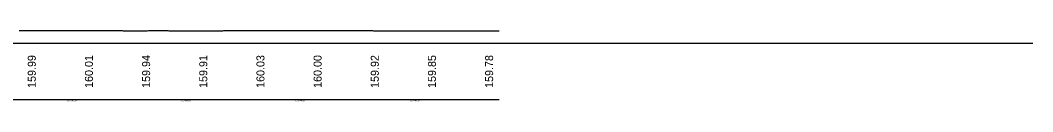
# Model space of a CAD drawing. Extents: x 2126510 to 2136144, y 865066 to 868066.
# Drawn here: x 2135258 to 2136144, y 867812 to 867874 of the extents above; entities that cross this region are included whole.
import ezdxf

# ---------------------------------------------------------------- set-up
doc = ezdxf.new("R2010")
doc.units = 0
doc.layers.add('RD_EX_Misc', color=7, linetype='Continuous')

msp = doc.modelspace()

# ---------------------------------------------------------------- linework, layer by layer
at = {"layer": 'RD_EX_Misc'}
msp.add_line((2131523, 867814.32), (2135677.25, 867814.32), dxfattribs=at)
for points in [[(2135257.47, 867874.35), (2135258.47, 867874.35), (2135259.47, 867874.35), (2135260.47, 867874.34), (2135261.47, 867874.34), (2135262.47, 867874.34), (2135263.47, 867874.33), (2135264.47, 867874.33), (2135265.47, 867874.33), (2135266.47, 867874.32), (2135267.47, 867874.32), (2135268.47, 867874.32), (2135269.47, 867874.32), (2135270.47, 867874.31), (2135271.47, 867874.31), (2135272.47, 867874.31), (2135273.47, 867874.3), (2135274.47, 867874.3), (2135275.47, 867874.3), (2135276.47, 867874.29), (2135277.47, 867874.29), (2135278.47, 867874.29), (2135279.47, 867874.29), (2135280.47, 867874.29), (2135281.47, 867874.29), (2135282.47, 867874.3), (2135283.47, 867874.3), (2135284.47, 867874.3), (2135285.47, 867874.3), (2135286.47, 867874.3)], [(2135286.47, 867874.3), (2135287.47, 867874.31), (2135288.47, 867874.31), (2135289.47, 867874.31), (2135290.47, 867874.31), (2135291.47, 867874.32), (2135292.47, 867874.32), (2135293.47, 867874.32), (2135294.47, 867874.32), (2135295.47, 867874.32), (2135296.47, 867874.33), (2135297.47, 867874.33), (2135298.47, 867874.33), (2135299.47, 867874.33), (2135300.47, 867874.33), (2135301.47, 867874.33), (2135302.47, 867874.33), (2135303.47, 867874.34), (2135304.47, 867874.34), (2135305.47, 867874.34), (2135306.47, 867874.34), (2135307.47, 867874.34), (2135308.47, 867874.34), (2135309.47, 867874.34), (2135310.47, 867874.34), (2135311.47, 867874.35), (2135312.47, 867874.35), (2135313.47, 867874.35), (2135314.47, 867874.35), (2135315.47, 867874.35), (2135316.47, 867874.35), (2135317.47, 867874.35), (2135318.47, 867874.34), (2135319.47, 867874.34), (2135320.47, 867874.33), (2135321.47, 867874.33), (2135322.47, 867874.33), (2135323.47, 867874.32), (2135324.47, 867874.32), (2135325.47, 867874.31), (2135326.47, 867874.31), (2135327.47, 867874.31), (2135328.47, 867874.3), (2135329.47, 867874.3), (2135330.47, 867874.29), (2135331.47, 867874.29), (2135332.47, 867874.28), (2135333.47, 867874.28), (2135334.47, 867874.28), (2135335.47, 867874.27), (2135336.47, 867874.27), (2135337.47, 867874.26), (2135338.47, 867874.26), (2135339.47, 867874.26), (2135340.47, 867874.26), (2135341.47, 867874.26), (2135342.47, 867874.26), (2135343.47, 867874.26), (2135344.47, 867874.25), (2135345.47, 867874.25), (2135346.47, 867874.25), (2135347.47, 867874.25), (2135348.47, 867874.24), (2135349.47, 867874.24), (2135350.47, 867874.24), (2135351.47, 867874.24), (2135352.47, 867874.24), (2135353.47, 867874.23), (2135354.47, 867874.23), (2135355.47, 867874.23), (2135356.47, 867874.23), (2135357.47, 867874.22), (2135358.47, 867874.22), (2135359.47, 867874.23), (2135360.47, 867874.23), (2135361.47, 867874.23), (2135362.47, 867874.23), (2135363.47, 867874.23), (2135364.47, 867874.24), (2135365.47, 867874.24), (2135366.47, 867874.24), (2135367.47, 867874.24), (2135368.47, 867874.24), (2135369.47, 867874.24), (2135370.47, 867874.25), (2135371.47, 867874.25), (2135372.47, 867874.25), (2135373.47, 867874.25), (2135374.47, 867874.25), (2135375.47, 867874.26), (2135376.47, 867874.26), (2135377.47, 867874.26), (2135378.47, 867874.26), (2135379.47, 867874.25), (2135380.47, 867874.25), (2135381.47, 867874.25), (2135382.47, 867874.25), (2135383.47, 867874.25), (2135384.47, 867874.25), (2135385.47, 867874.25), (2135386.47, 867874.25)], [(2135386.47, 867874.25), (2135387.47, 867874.25), (2135388.47, 867874.24), (2135389.47, 867874.24), (2135390.47, 867874.24), (2135391.47, 867874.24), (2135392.47, 867874.24), (2135393.47, 867874.24), (2135394.47, 867874.24), (2135395.47, 867874.24), (2135396.47, 867874.24), (2135397.47, 867874.23), (2135398.47, 867874.23), (2135399.47, 867874.23), (2135400.47, 867874.23), (2135401.47, 867874.23), (2135402.47, 867874.23), (2135403.47, 867874.23), (2135404.47, 867874.23), (2135405.47, 867874.23), (2135406.47, 867874.23), (2135407.47, 867874.23), (2135408.47, 867874.23), (2135409.47, 867874.22), (2135410.47, 867874.22), (2135411.47, 867874.22), (2135412.47, 867874.22), (2135413.47, 867874.22), (2135414.47, 867874.22), (2135415.47, 867874.22), (2135416.47, 867874.22), (2135417.47, 867874.22), (2135418.47, 867874.22), (2135419.47, 867874.22), (2135420.47, 867874.22), (2135421.47, 867874.22), (2135422.47, 867874.23), (2135423.47, 867874.23), (2135424.47, 867874.23), (2135425.47, 867874.23), (2135426.47, 867874.23), (2135427.47, 867874.23), (2135428.47, 867874.23), (2135429.47, 867874.24), (2135430.47, 867874.24), (2135431.47, 867874.24), (2135432.47, 867874.24), (2135433.47, 867874.24), (2135434.47, 867874.24), (2135435.47, 867874.24), (2135436.47, 867874.25), (2135437.47, 867874.25), (2135438.47, 867874.25), (2135439.47, 867874.25), (2135440.47, 867874.26), (2135441.47, 867874.26), (2135442.47, 867874.27), (2135443.47, 867874.27), (2135444.47, 867874.28), (2135445.47, 867874.28), (2135446.47, 867874.29), (2135447.47, 867874.29), (2135448.47, 867874.3), (2135449.47, 867874.3), (2135450.47, 867874.31), (2135451.47, 867874.31), (2135452.47, 867874.32), (2135453.47, 867874.32), (2135454.47, 867874.33), (2135455.47, 867874.33), (2135456.47, 867874.34), (2135457.47, 867874.34), (2135458.47, 867874.34), (2135459.47, 867874.34), (2135460.47, 867874.34), (2135461.47, 867874.34), (2135462.47, 867874.34), (2135463.47, 867874.34), (2135464.47, 867874.34), (2135465.47, 867874.34), (2135466.47, 867874.34), (2135467.47, 867874.34), (2135468.47, 867874.34), (2135469.47, 867874.34), (2135470.47, 867874.35), (2135471.47, 867874.35), (2135472.47, 867874.35), (2135473.47, 867874.35), (2135474.47, 867874.35), (2135475.47, 867874.35), (2135476.47, 867874.35), (2135477.47, 867874.35), (2135478.47, 867874.35), (2135479.47, 867874.35), (2135480.47, 867874.35), (2135481.47, 867874.35), (2135482.47, 867874.35), (2135483.47, 867874.35), (2135484.47, 867874.35), (2135485.47, 867874.35), (2135486.47, 867874.35)], [(2135486.47, 867874.35), (2135487.47, 867874.35), (2135488.47, 867874.35), (2135489.47, 867874.35), (2135490.47, 867874.35), (2135491.47, 867874.35), (2135492.47, 867874.35), (2135493.47, 867874.36), (2135494.47, 867874.36), (2135495.47, 867874.36), (2135496.47, 867874.36), (2135497.47, 867874.36), (2135498.47, 867874.35), (2135499.47, 867874.35), (2135500.47, 867874.35), (2135501.47, 867874.35), (2135502.47, 867874.35), (2135503.47, 867874.34), (2135504.47, 867874.34), (2135505.47, 867874.34), (2135506.47, 867874.34), (2135507.47, 867874.33), (2135508.47, 867874.33), (2135509.47, 867874.33), (2135510.47, 867874.33), (2135511.47, 867874.32), (2135512.47, 867874.32), (2135513.47, 867874.32), (2135514.47, 867874.32), (2135515.47, 867874.32), (2135516.47, 867874.31), (2135517.47, 867874.31), (2135518.47, 867874.31), (2135519.47, 867874.31), (2135520.47, 867874.31), (2135521.47, 867874.31), (2135522.47, 867874.31), (2135523.47, 867874.31), (2135524.47, 867874.31), (2135525.47, 867874.32), (2135526.47, 867874.32), (2135527.47, 867874.32), (2135528.47, 867874.32), (2135529.47, 867874.32), (2135530.47, 867874.32), (2135531.47, 867874.33), (2135532.47, 867874.33), (2135533.47, 867874.33), (2135534.47, 867874.33), (2135535.47, 867874.33), (2135536.47, 867874.33), (2135537.47, 867874.34), (2135538.47, 867874.34), (2135539.47, 867874.34), (2135540.47, 867874.34), (2135541.47, 867874.34), (2135542.47, 867874.33), (2135543.47, 867874.33), (2135544.47, 867874.33), (2135545.47, 867874.32), (2135546.47, 867874.32), (2135547.47, 867874.31), (2135548.47, 867874.31), (2135549.47, 867874.31), (2135550.47, 867874.3), (2135551.47, 867874.3), (2135552.47, 867874.3), (2135553.47, 867874.29), (2135554.47, 867874.29), (2135555.47, 867874.29), (2135556.47, 867874.28), (2135557.47, 867874.28), (2135558.47, 867874.28), (2135559.47, 867874.27), (2135560.47, 867874.27), (2135561.47, 867874.26), (2135562.47, 867874.26), (2135563.47, 867874.26), (2135564.47, 867874.25), (2135565.47, 867874.25), (2135566.47, 867874.25), (2135567.47, 867874.24), (2135568.47, 867874.24), (2135569.47, 867874.24), (2135570.47, 867874.24), (2135571.47, 867874.24), (2135572.47, 867874.23), (2135573.47, 867874.23), (2135574.47, 867874.23), (2135575.47, 867874.22), (2135576.47, 867874.22), (2135577.47, 867874.22), (2135578.47, 867874.22), (2135579.47, 867874.22), (2135580.47, 867874.23), (2135581.47, 867874.23), (2135582.47, 867874.23), (2135583.47, 867874.23), (2135584.47, 867874.23), (2135585.47, 867874.23), (2135586.47, 867874.23)], [(2135586.47, 867874.23), (2135587.47, 867874.23), (2135588.47, 867874.23), (2135589.47, 867874.24), (2135590.47, 867874.24), (2135591.47, 867874.24), (2135592.47, 867874.24), (2135593.47, 867874.24), (2135594.47, 867874.24), (2135595.47, 867874.24), (2135596.47, 867874.24), (2135597.47, 867874.24), (2135598.47, 867874.24), (2135599.47, 867874.23), (2135600.47, 867874.23), (2135601.47, 867874.22), (2135602.47, 867874.22), (2135603.47, 867874.21), (2135604.47, 867874.21), (2135605.47, 867874.2), (2135606.47, 867874.2), (2135607.47, 867874.19), (2135608.47, 867874.19), (2135609.47, 867874.18), (2135610.47, 867874.18), (2135611.47, 867874.17), (2135612.47, 867874.17), (2135613.47, 867874.16), (2135614.47, 867874.16), (2135615.47, 867874.16), (2135616.47, 867874.16), (2135617.47, 867874.17), (2135618.47, 867874.17), (2135619.47, 867874.17), (2135620.47, 867874.17), (2135621.47, 867874.17), (2135622.47, 867874.16), (2135623.47, 867874.16), (2135624.47, 867874.16), (2135625.47, 867874.16), (2135626.47, 867874.16), (2135627.47, 867874.16), (2135628.47, 867874.16), (2135629.47, 867874.16), (2135630.47, 867874.15), (2135631.47, 867874.15), (2135632.47, 867874.15), (2135633.47, 867874.15), (2135634.47, 867874.15), (2135635.47, 867874.15), (2135636.47, 867874.15), (2135637.47, 867874.15), (2135638.47, 867874.14), (2135639.47, 867874.14), (2135640.47, 867874.14), (2135641.47, 867874.14), (2135642.47, 867874.14), (2135643.47, 867874.14), (2135644.47, 867874.14), (2135645.47, 867874.13), (2135646.47, 867874.13), (2135647.47, 867874.13), (2135648.47, 867874.13), (2135649.47, 867874.13), (2135650.47, 867874.13), (2135651.47, 867874.13), (2135652.47, 867874.12), (2135653.47, 867874.12), (2135654.47, 867874.12), (2135655.47, 867874.12), (2135656.47, 867874.12), (2135657.47, 867874.12), (2135658.47, 867874.12), (2135659.47, 867874.11), (2135660.47, 867874.11), (2135661.47, 867874.11), (2135662.47, 867874.11), (2135663.47, 867874.11), (2135664.47, 867874.11), (2135665.47, 867874.11), (2135666.47, 867874.1), (2135667.47, 867874.1), (2135668.47, 867874.1), (2135669.47, 867874.1), (2135670.47, 867874.1), (2135671.47, 867874.1), (2135672.47, 867874.1), (2135673.47, 867874.09), (2135674.47, 867874.09), (2135675.47, 867874.09), (2135676.47, 867874.09), (2135677.25, 867874.09)], [(2131430.13, 867814.32), (2131430.13, 867863.32), (2136143.96, 867863.32)]]:
    msp.add_lwpolyline(points, dxfattribs=at)

# ---------------------------------------------------------------- texts
for s, p in [('159.99', (2135272, 867824.32)), ('160.01', (2135322, 867824.32)), ('159.94', (2135372, 867824.32)), ('159.91', (2135422, 867824.32)), ('160.03', (2135472, 867824.32)), ('160.00', (2135522, 867824.32)), ('159.92', (2135572, 867824.32)), ('159.85', (2135622, 867824.32)), ('159.78', (2135672, 867824.32))]:
    msp.add_text(s, height=7, rotation=90, dxfattribs=at).set_placement(p)
for s, p in [('1827+00', (2135298.79, 867812.52)), ('1828+00', (2135398.79, 867812.52)), ('1829+00', (2135498.79, 867812.52)), ('1830+00', (2135598.79, 867812.52))]:
    msp.add_text(s, height=1.6, dxfattribs=at).set_placement(p)

doc.saveas('drawing.dxf')
